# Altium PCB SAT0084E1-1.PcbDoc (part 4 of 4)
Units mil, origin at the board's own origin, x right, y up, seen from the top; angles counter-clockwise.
Board outline 7055 x 5555 mil, 6 copper layers (Top Layer, MidLayer1-GND, MidLayer2-HiSp, MidLayer3-GND, MidLayer4, Bottom Layer), stack 57.4 mil thick; 379 components, 207 nets, 1026 pads, 1546 vias.
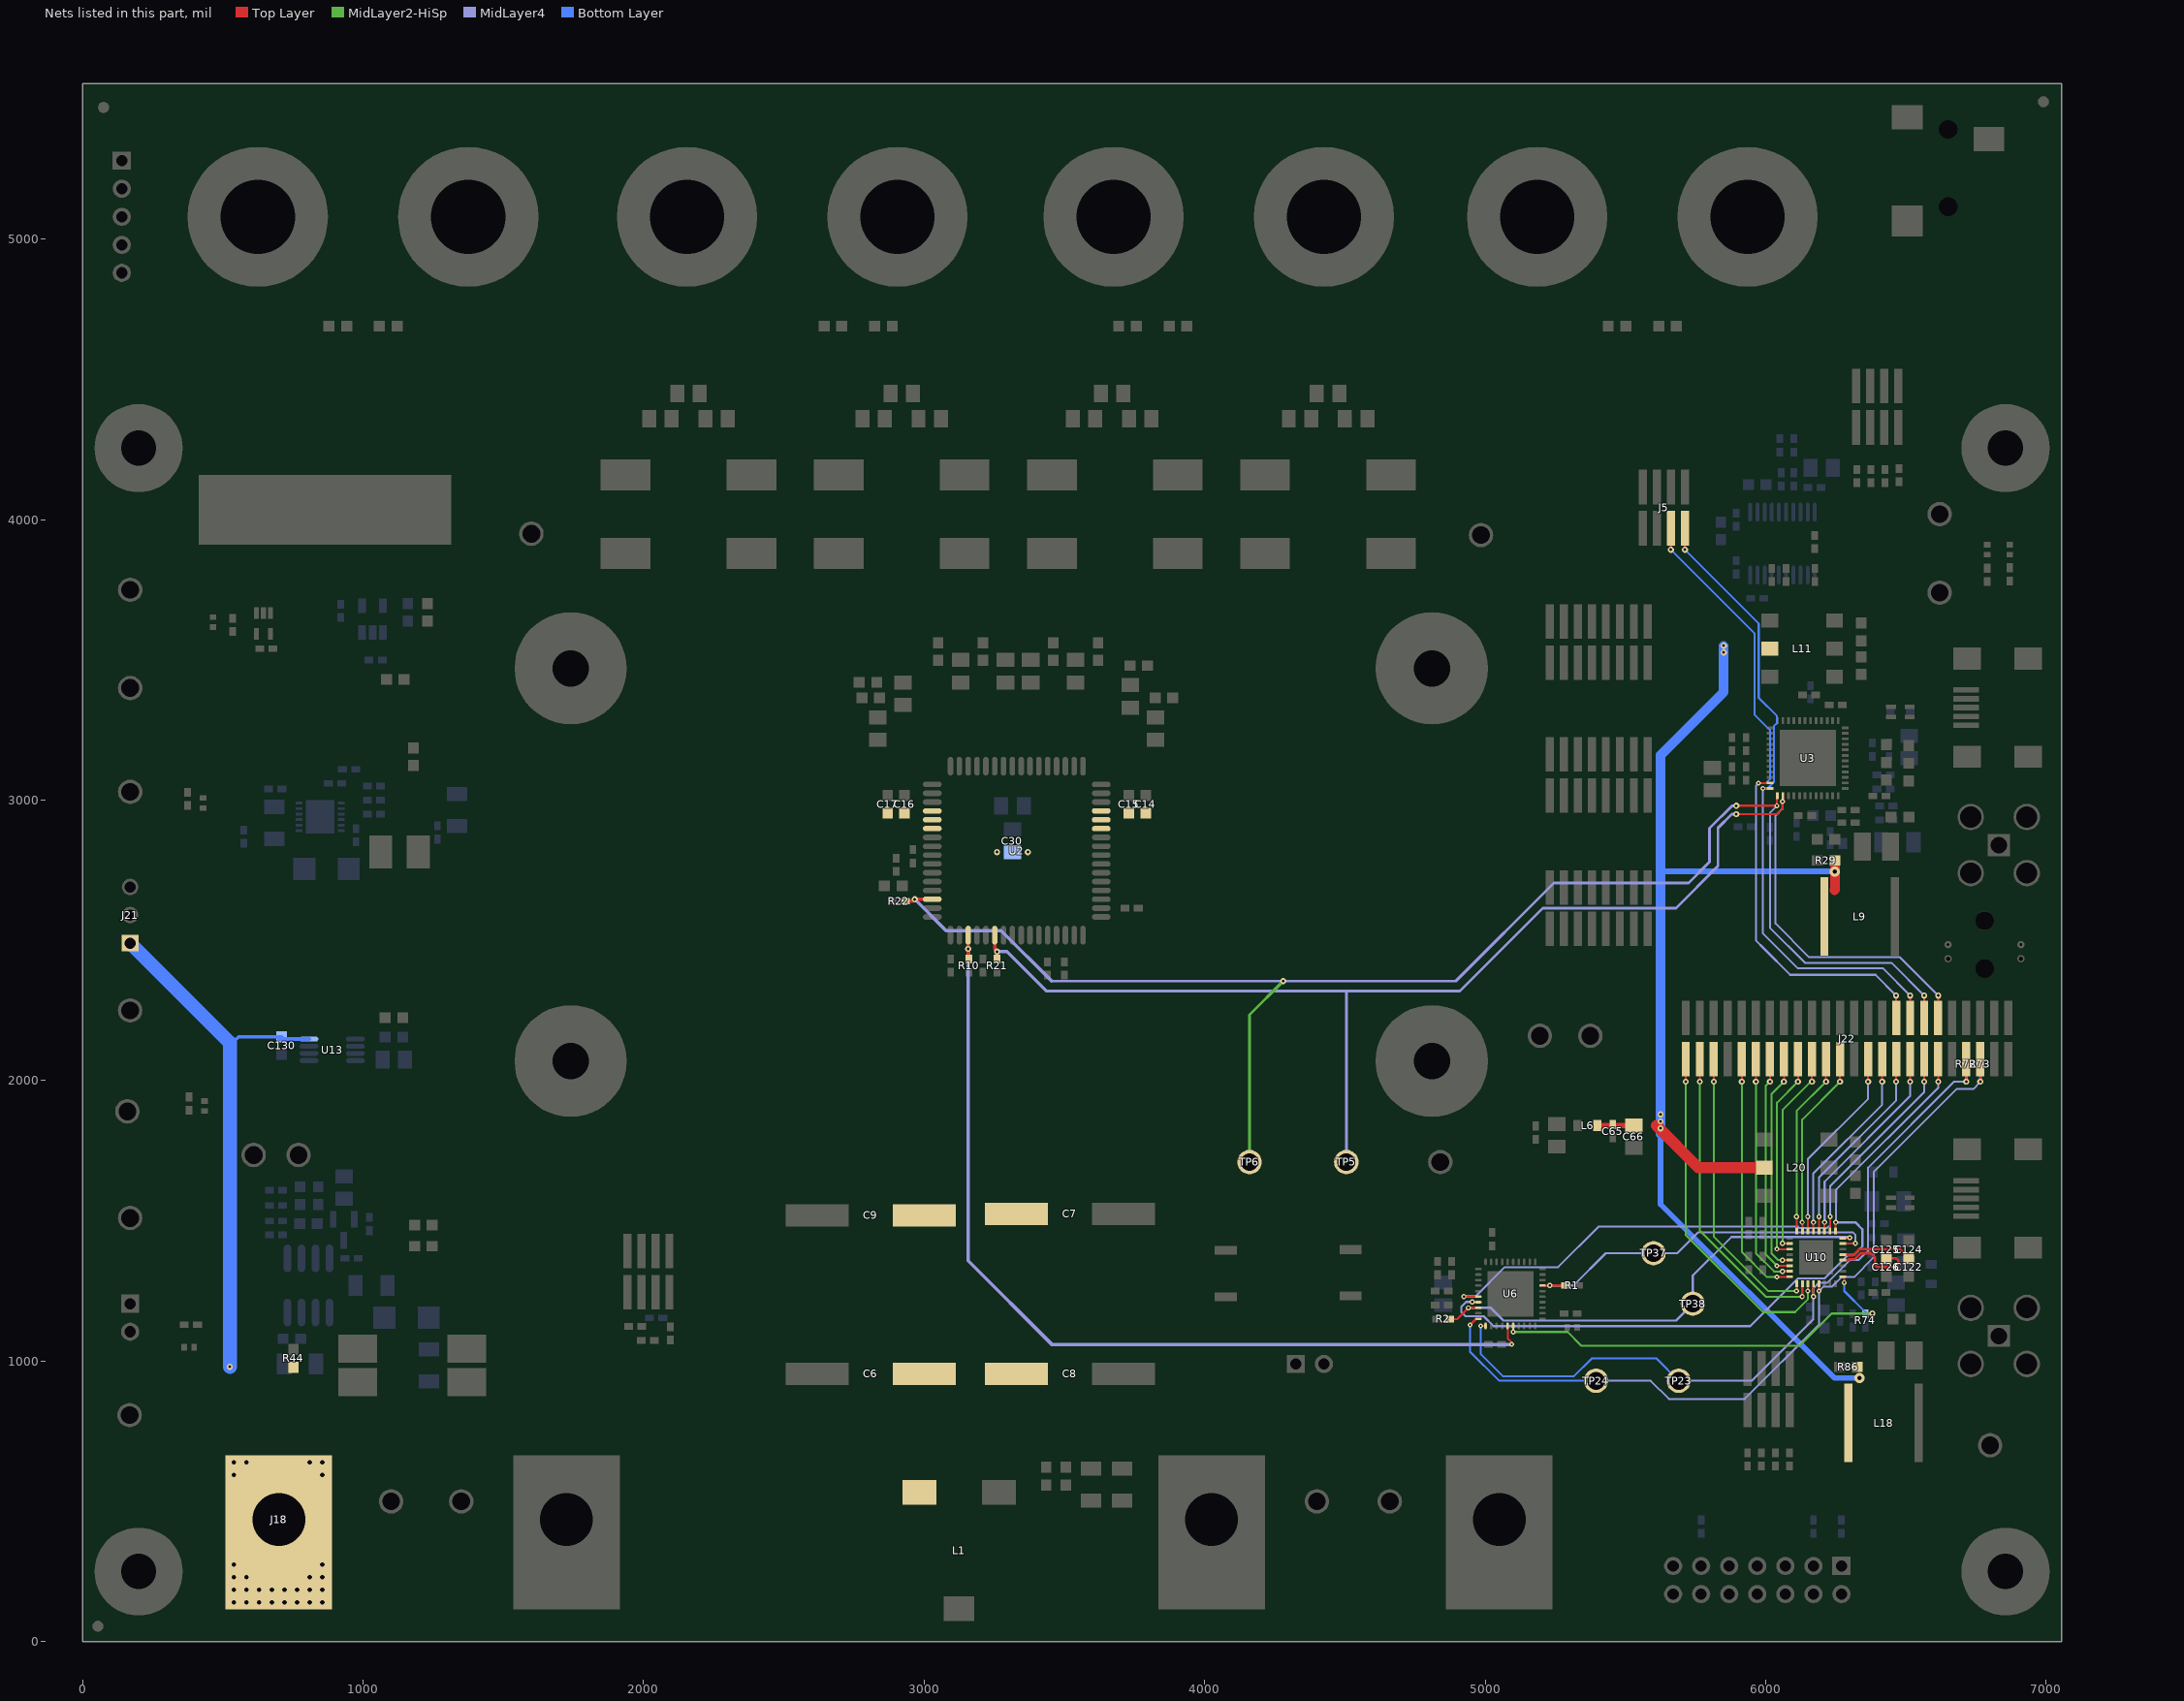
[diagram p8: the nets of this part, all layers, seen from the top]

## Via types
v1: diameter 22, hole 10, Top Layer to Bottom Layer, tented both sides, 1179 vias
v2: diameter 48, hole 22, Top Layer to Bottom Layer, tented both sides, 128 vias
v3: diameter 32, hole 16, Top Layer to Bottom Layer, tented both sides, 112 vias
v4: diameter 18, hole 8, Top Layer to Bottom Layer, tented both sides, 80 vias
v5: diameter 19.68, hole 7.87, Top Layer to Bottom Layer, tented both sides, 30 vias
v6: diameter 26, hole 16, Top Layer to Bottom Layer, 12 vias
v7: diameter 36, hole 16, Top Layer to Bottom Layer, tented both sides, 2 vias
v8: diameter 26, hole 10, Top Layer to Bottom Layer, tented both sides, 1 vias
v9: diameter 20, hole 8, Top Layer to Bottom Layer, tented both sides, 1 vias
v10: diameter 30, hole 12, Top Layer to Bottom Layer, tented both sides, 1 vias

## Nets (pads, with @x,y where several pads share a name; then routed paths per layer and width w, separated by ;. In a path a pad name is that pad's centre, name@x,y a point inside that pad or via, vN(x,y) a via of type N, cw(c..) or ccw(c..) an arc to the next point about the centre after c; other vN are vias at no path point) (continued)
PCM_MUTE_2: J5.5 J22.32 U3.23 | length 2355.7
  Top Layer w7: v4@5974,3061.42 U3.23@6016.14,3061.42
  Top Layer w8: v1(5662,3893) J5.5@5662,3969.48 ; J22.32@6465,2223.52 v1(6465,2303.52)
  MidLayer4 w7: v4(5974,3061) 5965,3052 5965,2500 5995,2470
  MidLayer4 w8: 5995,2470 6087.5,2377.5 6391.02,2377.5 v1(6465,2303.52)
  Bottom Layer w7: v1(5662,3893) 5960,3595 5960,3305 6015,3250 6015,3075 6001.37,3061.37 5974.37,3061.37 v4(5974,3061)
PCM_MUTE_3: J5.7 J22.34 U3.24 | length 2333.7
  Top Layer w7: v1(5712,3893) J5.7@5712,3969.48 ; v4@5990,3042 v4(5990.13,3041.87) 5990.27,3041.73 U3.24@6016.14,3041.73 ; J22.34@6515,2223.52 v1(6515,2303.52)
  MidLayer4 w7: v4(5990.13,3041.87) 5990.13,2524.87 6115,2400 6418.52,2400 v1(6515,2303.52)
  Bottom Layer w7: v1(5712,3893) 5975,3630 5975,3365 6040,3300 6040,3275 6030,3265 6030,3065 6006.87,3041.87 v4(5990.13,3041.87)
POC: C65.1 C66.1 L6.2 L9.1 L11.5 L18.1 L20.5 R29.2 R86.2 | length 4356.5
  Top Layer w20: L6.2@5400,1845 5405,1840 C66.1@5530,1840
  Top Layer w35: 6245,2680 6246.5,2681.5 R29.2@6246.5,2785
  Top Layer w40: 5610,1840 5760,1690 L20.5@5994.84,1690
  Bottom Layer w20: 5625,1810 5625.5,1809.5 5625.5,1559.5 6245,940 v7(6335,940) ; 5625,2744 5627,2746 v7(6246,2746)
  Bottom Layer w35: 5625,1810 v1(5625,1830) v1(5625,1855) v1(5625,1880) 5625,2744 5625,3160 5850,3385 v1@5850,3550
  other v1: 5850,3527 5850,3551
PVDD: C6.1 C7.1 C8.1 C9.1 C14.1 C15.1 C16.1 C17.1 C30.1 L1.2 U2.27 U2.28 U2.29 U2.52 U2.53 U2.54
  other v1: 3260,2815 3370,2815
SER_CLIP_OTW: J22.37 U6.7 U10.17 | length 2584.8
  Top Layer w7: v4(4954,1211) 4954.53,1210.47 U6.7@4975.83,1210.47 ; U10.17@6248.9,1464.49 v4@6248.9,1488.9 ; v4@6248.9,1493.9 v4(6250,1495) ; v1(6615,1996.48) J22.37@6615,2076.48
  MidLayer4 w7: v4@6250,1490 v4(6250,1495) 6250,1610 6615,1975 v1(6615,1996.48)
  MidLayer4 w8: v4(4954,1211) 4932,1211 4915,1194 4915,1175 4930,1160 4995,1160 5030,1125 5945,1125 6115,1295 6210,1295 6295,1380 6315,1380 6345,1410 6345,1470 6320,1495 v4(6250,1495)
SER_DOUT_N: C125.1 C126.1 U10.12 | length 309.9
  Top Layer w9: U10.12@6274.49,1360.16 6294,1360.16 6296.84,1363 6316.8,1363 6338.8,1385 6375,1385 6390,1370 6390,1343 6398,1335 6465,1335 6472,1342 6472,1360 6465.5,1366.5 C125.1@6430,1366.5
SER_DOUT_P: C122.1 C124.1 U10.13 | length 265.4
  Top Layer w9: U10.13@6274.49,1379.84 6294,1379.84 6296.84,1377 6311,1377 6333,1399 6479.5,1399 C122.1@6510,1368.5 ; C122.1@6503,1365 C122.1@6510,1365
SER_FAULT: J22.35 U6.6 U10.18 | length 2242.4
  Top Layer w7: v4@4924,1230.5 4975.48,1230.5 U6.6@4975.83,1230.16 ; U10.18@6229.21,1464.49 6229.5,1464.78 v4@6229.5,1509.5 ; v4@6229.5,1514.5 v4(6230,1515) ; v1(6565,1996.48) J22.35@6565,2076.48
  MidLayer4 w7: v4@4924,1232 4967,1232 5070,1335 5260,1335 5405,1480 6114,1480 6119,1475 6219,1475 6230,1486 6230,1625 6565,1960 v1(6565,1996.48)
  other v4: 4924,1230
SER_GPO2: R2.2 TP38.1 U6.8 U10.16 | length 1706.6
  Top Layer w7: U10.16@6274.49,1438.9 6298.9,1438.9 v4(6300,1440)
  Top Layer w8: R2.2@4873.62,1150 4900,1150 v4(4940,1190) v4@4945,1190 ; v4@4945,1190.79 U6.8@4975.83,1190.79
  MidLayer4 w8: v4(4940,1190) 5020,1190 5065,1145 5680,1145 TP38.1@5740,1205 5740,1305 5878,1443 6297,1443 v4(6300,1440)
SER_GPO3: R1.2 TP37.1 U6.27 U10.15 | length 1331.1
  Top Layer w7: U6.27@5204.17,1269.53 5229.53,1269.53 v4(5230,1270) R1.2@5286.38,1270 ; U10.15@6274.49,1419.21 6274.78,1419.5 6319.5,1419.5 v4(6320,1420)
  MidLayer4 w7: v4(5230,1270) 5315,1270 5430,1385 TP37.1@5600,1385 5685,1385 5760,1460 6310,1460 6320,1450 v4(6320,1420)
SER_I2C_SCL: J22.41 R72.1 TP23.1 U6.11 U10.4 | length 2786.1
  Top Layer w7: v4(6170,1230) 6170.16,1230.16 U10.4@6170.16,1275.51 ; v1(6715,1996.48) J22.41@6715,2076.48
  Top Layer w8: v4(4984,1126) 4984.17,1125.83 U6.11@5001.42,1125.83
  MidLayer4 w7: TP23.1@5690,930 5950,930 6170,1150 v4(6170,1230) 6170,1260 6190,1280 6220,1280 6300,1360 6330,1360 6365,1395 6365,1690 6671.48,1996.48 v1(6715,1996.48)
  Bottom Layer w7: v4(4984,1126) 4984,1026 5064.38,945.62 5315.62,945.62 5380,1010 5610,1010 TP23.1@5690,930
  Bottom Layer w10: v1(6715,1996.48) R72.1@6715,2036.38
SER_I2C_SDA: J22.43 R73.1 TP24.1 U6.10 U10.5 | length 2887.1
  Top Layer w7: U10.5@6189.84,1275.51 6189.84,1250.16 v4(6190,1250) ; v1(6765,1996.48) J22.43@6765,2076.48
  Top Layer w8: v4(4946,1129) 4968.42,1151.42 U6.10@4975.83,1151.42
  MidLayer4 w7: TP24.1@5435,930 5590,930 5655,865 5925,865 6190,1130 v4(6190,1250) 6205,1265 6235,1265 6270,1300 6315,1300 6385,1370 6385,1675 6680,1970 6740,1970 6765,1995 v1(6765,1996.48)
  Bottom Layer w7: v4(4946,1129) 4946,1034 5050,930 TP24.1@5435,930
  Bottom Layer w10: v1(6765,1996.48) R73.1@6765,2036.38
SER_I2S_BCK: J22.5 U10.1 | length 1033.2
  Top Layer w7: v1(5815,1996.48) J22.5@5815,2076.48 ; v4(6110,1250) 6111.1,1251.1 U10.1@6111.1,1275.51
  MidLayer2-HiSp w7: v1(5815,1996.48) 5815,1445 6010,1250 v4(6110,1250)
SER_I2S_DATA0: J22.9 U10.32 | length 894.7
  Top Layer w7: v1(5915,1996.48) J22.9@5915,2076.48 ; v4(6040,1300) 6040.5,1300.5 6084.91,1300.5 U10.32@6085.51,1301.1
  MidLayer2-HiSp w7: v1(5915,1996.48) 5915,1390 6005,1300 v4(6040,1300)
SER_I2S_DATA1: J22.11 U10.31 | length 837.8
  Top Layer w7: v1(5965,1996.48) J22.11@5965,2076.48 ; v4(6060,1320) 6060.79,1320.79 U10.31@6085.51,1320.79
  MidLayer2-HiSp w7: v1@5965,1995 5965,1385 6030,1320 v4(6060,1320)
SER_I2S_DATA2: J22.13 U10.30 | length 805
  Top Layer w7: v1(6015,1996.48) J22.13@6015,2076.48 ; v4(6040,1340) 6040.47,1340.47 U10.30@6085.51,1340.47
  MidLayer2-HiSp w7: v1(6015,1996.48) 6000,1981.48 6000,1380 v4(6040,1340)
SER_I2S_DATA3: J22.15 U10.29 | length 786
  Top Layer w7: v4(6060,1360) 6060.16,1360.16 U10.29@6085.51,1360.16 ; v1(6065,1996.48) J22.15@6065,2076.48
  MidLayer2-HiSp w7: v4(6060,1360) 6045,1360 6020,1385 6020,1951.48 v1(6065,1996.48)
SER_I2S_DATA4: J22.17 U10.27 | length 753.2
  Top Layer w7: v4(6040,1400) 6040.47,1399.53 U10.27@6085.51,1399.53 ; v1(6115,1996.48) J22.17@6115,2076.48
  MidLayer2-HiSp w7: v4(6040,1400) 6040,1921.48 v1(6115,1996.48)
SER_I2S_DATA5: J22.19 U10.26 | length 729.3
  Top Layer w7: v4(6060,1420) 6060.79,1419.21 U10.26@6085.51,1419.21 ; v1(6165,1996.48) J22.19@6165,2076.48
  MidLayer2-HiSp w7: v4(6060,1420) 6060,1895 6160,1995 v1@6165,1990
SER_I2S_DATA6: J22.21 U10.24 | length 655.9
  Top Layer w7: v4(6110,1515) v4@6110.5,1514.5 ; v4@6110.5,1509.5 6110.5,1465.09 U10.24@6111.1,1464.49 ; v1(6215,1996.48) J22.21@6215,2076.48
  MidLayer2-HiSp w7: v4@6110,1510 v4(6110,1515) 6110,1891.48 v1(6215,1996.48)
SER_I2S_DATA7: J22.23 U10.23 | length 668.2
  Top Layer w7: v4(6130,1495) v4@6130.79,1494.21 ; U10.23@6130.79,1464.49 v4@6130.79,1489.21 ; v1(6265,1996.48) J22.23@6265,2076.48
  MidLayer2-HiSp w7: v4@6130,1490 v4(6130,1495) 6130,1861.48 v1(6265,1996.48)
SER_I2S_LRCK: J22.3 U10.2 | length 1119.7
  Top Layer w7: v1(5765,1996.48) J22.3@5765,2076.48 ; v4(6130,1230) 6130.5,1230.5 6130.5,1275.22 U10.2@6130.79,1275.51
  MidLayer2-HiSp w7: v1(5765,1996.48) 5765,1465 6000,1230 v4(6130,1230)
SER_I2S_SCK: J22.1 U10.3 | length 1249.7
  Top Layer w7: v1(5715,1996.48) J22.1@5715,2076.48 ; v4(6150,1250) 6150.47,1250.47 U10.3@6150.47,1275.51
  MidLayer2-HiSp w7: v1(5715,1996.48) 5715,1957.35 5715,1450 5990,1175 6105,1175 6150,1220 v4(6150,1250)
SER_MUTE_0: J22.27 U10.22 | length 701.2
  Top Layer w7: v4(6150,1515) v4@6150.47,1514.53 ; U10.22@6150.47,1464.49 v4@6150.47,1509.53 ; v1(6365,1996.48) J22.27@6365,2076.48
  MidLayer4 w7: v4@6150,1510 6150,1720 6365,1935 v1(6365,1996.48)
SER_MUTE_1: J22.29 U10.21 | length 713.5
  Top Layer w7: v4(6170,1495) v4@6170.16,1494.84 ; U10.21@6170.16,1464.49 v4@6170.16,1489.84 ; v1(6415,1996.48) J22.29@6415,2076.48
  MidLayer4 w7: v4@6170,1490 6170,1670 6415,1915 v1(6415,1996.48)
SER_MUTE_2: J22.31 U10.20 | length 726
  Top Layer w7: U10.20@6189.84,1464.49 v4@6189.84,1509.84 ; v4@6189.84,1514.84 v4(6190,1515) ; v1(6465,1996.48) J22.31@6465,2076.48
  MidLayer4 w7: v4@6190,1510 6190,1655 6465,1930 v1(6465,1996.48)
SER_MUTE_3: J22.33 U10.19 | length 738.5
  Top Layer w7: U10.19@6209.53,1464.49 v4@6209.53,1489.53 ; v4@6209.53,1494.53 v4(6210,1495) ; v1(6515,1996.48) J22.33@6515,2076.48
  MidLayer4 w7: v4@6210,1490 6210,1640 6515,1945 v1(6515,1996.48)
SER_PDB: R74.1 U6.16 U10.9 | length 1563.8
  Top Layer w7: U6.16@5099.84,1125.83 5099.84,1104.16 v4(5100,1104) ; U10.9@6274.49,1301.1 6278.9,1301.1 6280,1300 v4(6280,1280)
  MidLayer2-HiSp w8: v4(5100,1104) 5294,1104 5343,1055 6120,1055 6235,1170 v1(6380,1170)
  Bottom Layer w8: v4(6280,1280) 6280,1250 6355,1175 R74.1@6355,1168.62
  Bottom Layer w10: R74.1@6355,1168.62 6378.62,1168.62 v1(6380,1170)
TAS_CLIP_OTW: J22.38 R21.1 TP5.1 U2.6 U3.26 | length 5163.9
  Top Layer w7: v4(6060,2995) 6061.42,2996.42 U3.26@6061.42,3016.14 ; J22.38@6615,2223.52 v1(6615,2303.52)
  Top Layer w8: v1(5895,2950) 6040,2950 6060,2970 v4(6060,2995)
  Top Layer w12: U2.6@3251.57,2518.82 3251.57,2468.43 v1(3260,2460) R21.1@3260,2433.62
  MidLayer4 w7: v4(6060,2995) 6060,2970 6035,2945 6035,2560 6155,2440 6478.52,2440 v1(6615,2303.52)
  MidLayer4 w10: 3435,2320 4505,2320 ; TP5.1@4505,1710 4505,2320 ; v1(5895,2950) 5879,2950 5830,2901 5830,2765 5680,2615 5205,2615 4910,2320 4505,2320
  MidLayer4 w12: v1(3260,2460) 3295,2460 3435,2320
TAS_FAULT: J22.36 R22.1 TP6.1 U2.62 U3.25 | length 5528.5
  Top Layer w7: v4(6040,2980) 6040.5,2980.5 6040.5,3014.91 U3.25@6041.73,3016.14 ; J22.36@6565,2223.52 v1(6565,2303.52)
  Top Layer w8: v1(5895,2980) v4(6040,2980)
  Top Layer w12: R22.1@2933.62,2640 2960,2640 v1(2966.77,2646.77) U2.62@3029.13,2646.77
  MidLayer2-HiSp w10: TP6.1@4160,1710 4160,2235 v1(4280,2355)
  MidLayer4 w7: v4(6040,2980) 6015,2955 6015,2545 6140,2420 6448.52,2420 v1(6565,2303.52)
  MidLayer4 w10: 3455,2355 v1(4280,2355) 4895,2355 5245,2705 5725,2705 5800,2780 5800,2900 5880,2980 v1(5895,2980)
  MidLayer4 w12: v1(2966.77,2646.77) 3078.54,2535 3275,2535 3455,2355
TAS_STANDBY: R10.1 U2.3 U6.15 | length 3332.7
  Top Layer w7: U6.15@5080.16,1125.83 5080.16,1080.87 5095,1066.03 v4@5095,1065
  Top Layer w12: R10.1@3157.09,2426.54 v1(3157.09,2470) U2.3@3157.09,2518.82
  MidLayer4 w12: v1(3157.09,2470) 3157.09,1357.91 3455,1060 v4(5095,1060)
VBAT: C130.1 J18.1 J21.1 R44.1 U13.8 | length 1946.9
  Bottom Layer w12: 535,2135 556.5,2156.5 C130.1@710,2156.5
  Bottom Layer w15: C130.1@701.9,2148.39 U13.8@807.32,2148.39
  Bottom Layer w50: J21.1@169.87,2490.5 525,2135.37 v1(525,980)
  other v3: 540,140 585,140 630,140 675,140 720,140 765,140 810,140 855,140 540,185 585,185 630,185 675,185 720,185 765,185 810,185 855,185 540,230 585,230 810,230 855,230 540,275 855,275 540,595 855,595 540,640 585,640 810,640 855,640
pads on no net: FID1.1 FID2.1 FID3.1 FID4.1 FID5.1 FID6.1 H1.1 H2.1 H3.1 H4.1 H10.0 H11.0 H12.0 H13.0 H14.0 H15.0 H16.0 H17.0 J4.4 J4.5 J15.1 J15.4 J15.5 J17.6 J17.10 J17.12 J17.13 J17.14 J25.1 J25.4 J25.5 J26.MH1 J26.MH2 L1.3 L11.2 L11.4 L11.6 L20.2 L20.4 L20.6 SH-J21.0 SH-J24.0 SH-J27.0 U3.32 U3.33

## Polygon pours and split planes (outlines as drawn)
NetC97_2 on Top Layer "Top Layer-No Net 1" (solid, remove dead copper, pour order 43): 1105,2910 1105,2720 990,2720 990,2820 1020,2850 1065,2910
3V3 on Top Layer "Top Layer-No Net 1" (solid, remove dead copper, pour order 41): 5870,3135 5870,3110 6005.71,3110 6018.57,3119 6018.57,3123 6018.57,3134 6020,3135
1V8 on Top Layer "Top Layer-No Net 1" (solid, remove dead copper, pour order 40): 5920,3190 6025,3190 6025,3170 5965,3170 5960,3165 5870,3165 5870,3190
NetC28_1 on Top Layer "Top Layer-No Net 1" (solid, remove dead copper, pour order 57): 1105,5390 1100,5385 1100,4595 1190,4505 2240,4505 2265,4480 2265,4300 2295,4270 2295,4100 2475,4100 2475,4480 2235,4720 1925,4720 1650,4995 1650,5390
NetC31_2 on Top Layer "Top Layer-No Net 1" (solid, remove dead copper, pour order 59): 355,5390 355,4655 740,4270 1760,4270 1830,4200 1830,4095 2050,4095 2050,4485 1075,4485 900,4660 900,5390
NetC37_1 on Top Layer "Top Layer-No Net 1" (solid, remove dead copper, pour order 55): 2560,5390 2560,4880 2675,4765 2685,4755 2840,4755 2860,4735 2865,4730 2865,4665 2865,4645 3030,4480 3035,4475 3035,4105 3035,4100 3240,4100 3240,5390
NetC47_2 on Top Layer "Top Layer-No Net 1" (solid, remove dead copper, pour order 54): 3340,5390 3340,4100 3555,4100 3555,4480 3715,4640 3715,4720 3715,4725 3745,4755 3915,4755 3925,4755 4005,4835 4005,5390
NetC39_2 on Top Layer "Top Layer-No Net 1" (solid, remove dead copper, pour order 56): 1865,5390 1865,4900 2015,4750 2240,4750 2605,4385 2605,4100 2805,4100 2805,4525 2665,4665 2665,4725 2525,4865 2525,5390
NetC45_1 on Top Layer "Top Layer-No Net 1" (solid, remove dead copper, pour order 53): 3780,4100 3780,4530 3915,4665 3915,4710 4085,4880 4085,5390 4750,5390 4750,4965 4585,4800 4340,4800 4010,4470 4010,4100
NetC52_1 on Top Layer "Top Layer-No Net 1" (solid, remove dead copper, pour order 60): 6250,5390 6250,4655 5865,4270 4845,4270 4775,4200 4775,4095 4555,4095 4555,4485 5490,4485 5660,4655 5660,5390
OUT3_P on Top Layer "Top Layer-No Net 1" (solid, remove dead copper, pour order 44): 3462,3100 3462,3330 3507,3375 3562,3375 3562,3217 3515,3170 3497,3170 3482,3155 3482,3100
OUT4_M on Top Layer "Top Layer-No Net 1" (solid, remove dead copper, pour order 50): 3545,3095 3545,3155 3560,3170 3585,3170 3610,3195 3730,3195 3775,3240 3775,3295 3600,3295 3570,3265 3570,3215 3525,3170 3525,3095
OUT4_P on Top Layer "Top Layer-No Net 1" (solid, remove dead copper, pour order 49): 3790,3180 3610,3180 3585,3155 3555,3155 3555,3080 3745,3080 3750,3080 3790,3120
OUT1_M on Top Layer "Top Layer-No Net 1" (solid, remove dead copper, pour order 48): 2870,3180 3050,3180 3075,3155 3095,3155 3105,3145 3105,3080 2910,3080 2870,3120
OUT2_P on Top Layer "Top Layer-No Net 1" (solid, remove dead copper, pour order 46): 3245,3375 3210,3340 3210,3100 3230,3100 3230,3155 3245,3170 3270,3170 3310,3210 3310,3375
OUT3_M on Top Layer "Top Layer-No Net 1" (solid, remove dead copper, pour order 45): 3450,3100 3450,3330 3405,3375 3350,3375 3350,3210 3390,3170 3415,3170 3430,3155 3430,3100
OUT2_M on Top Layer "Top Layer-No Net 1" (solid, remove dead copper, pour order 47): 3100,3375 3100,3220 3150,3170 3160,3170 3175,3155 3175,3095 3200,3095 3200,3340 3165,3375
OUT1_P on Top Layer "Top Layer-No Net 1" (solid, remove dead copper, pour order 51): 3115,3095 3115,3155 3100,3170 3075,3170 3040,3205 2921,3205 2885,3241 2885,3306 3049,3306 3085,3270 3085,3215 3135,3165 3135,3095
NetC54_2 on Top Layer "Top Layer-No Net 1" (solid, remove dead copper, pour order 58): 5455,5390 5455,4550 5410,4505 4360,4505 4335,4480 4335,4300 4305,4270 4305,4100 4125,4100 4125,4500 4380,4755 4615,4755 4845,4985 4845,5390
3V3 on Top Layer "Top Layer-No Net 1" (solid, remove dead copper, pour order 42): 5930,1435 6095,1435 6095,1445 6075,1445 6055,1465 5930,1465
VBAT on Top Layer "Top Layer-No Net 1" (solid, remove dead copper, pour order 52): 505,115 500,120 500,1000 785,1000 785,870 890,765 890,115
PVDD on Top Layer "Top Layer-No Net 1" (solid, remove dead copper, pour order 61): 2810,485 3055,485 3150,580 3150,610 3205,665 3235,665 3520,950 3520,1575 3690,1745 4010,1745 4250,1985 4250,2875 4150,2975 3485,2975 3355,2845 3355,2790 3395,2790 3490,2885 3755,2885 3885,2755 3885,2550 3655,2320 3025,2320 2795,2550 2795,2800 2880,2885 3130,2885 3225,2790 3275,2790 3275,2845 3145,2975 2485,2975 2385,2875 2385,2000 2810,1575
GND on Top Layer "Top Layer-No Net 1" (solid, remove dead copper, pour order 62): 25,5525 7025,5525 7025,25 25,25
OUT1_M on MidLayer2-HiSp "Top Layer-No Net 1" (solid, remove dead copper, pour order 67): 2010,3960 2010,3700 2130,3580 2370,3580 2880,3070 3080,3070 3080,3130 3020,3190 2920,3190 2870,3240 2870,3310 2460,3720 2170,3720 2150,3740 2150,3960
OUT2_M on MidLayer2-HiSp "Top Layer-No Net 1" (solid, remove dead copper, pour order 64): 2770,3960 2770,3710 2880,3600 2990,3600 3080,3510 3080,3240 3150,3170 3200,3170 3200,3580 3050,3730 2960,3730 2910,3780 2910,3960
OUT3_M on MidLayer2-HiSp "Top Layer-No Net 1" (solid, remove dead copper, pour order 65): 3340,3210 3340,3460 3410,3530 3470,3530 3530,3590 3530,3960 3670,3960 3670,3470 3600,3400 3500,3400 3450,3350 3450,3170 3380,3170
OUT4_M on MidLayer2-HiSp "Top Layer-No Net 1" (solid, remove dead copper, pour order 66): 3570,3260 3630,3320 3920,3320 4290,3690 4290,3960 4430,3960 4430,3560 4060,3190 3570,3190
GND on MidLayer3-GND "Top Layer-No Net 1" (solid, remove dead copper, pour order 72): 25,5525 7025,5525 7025,25 25,25
OUT4_P on MidLayer3-GND "Top Layer-No Net 1" (solid, remove dead copper, pour order 71): 3620,3180 3580,3140 3580,3070 3940,3070 4590,3720 4590,3960 4450,3960 4450,3770 4420,3740 4340,3740 3835,3235 3790,3235 3735,3180
OUT3_P on MidLayer3-GND "Top Layer-No Net 1" (solid, remove dead copper, pour order 69): 3460,3170 3460,3520 3530,3590 3530,3670 3590,3730 3650,3730 3690,3770 3690,3960 3830,3960 3830,3730 3670,3570 3670,3470 3560,3360 3560,3210 3520,3170
OUT2_P on MidLayer3-GND "Top Layer-No Net 1" (solid, remove dead copper, pour order 68): 3210,3170 3210,3340 3170,3380 3080,3380 3080,3510 2930,3660 2930,3960 3070,3960 3070,3710 3200,3580 3200,3490 3320,3370 3320,3220 3270,3170
OUT1_P on MidLayer3-GND "Top Layer-No Net 1" (solid, remove dead copper, pour order 70): 2170,3960 2170,3650 2240,3580 2370,3580 2760,3190 3090,3190 3090,3250 3020,3320 2860,3320 2460,3720 2330,3720 2310,3740 2310,3960
GND on MidLayer4 "Top Layer-No Net 1" (solid, remove dead copper, pour order 73): 6354,3150 6565,3150 6665,3050 6665,2840 6975,2530 6975,2390 6665,2390 6500,2555 6500,2965 6450,3015 6305,3015 6305,3101
NetC97_2 on Bottom Layer "Top Layer-No Net 1" (solid, remove dead copper, pour order 76): 910,2895 910,2715 1020,2715 1020,2810 1010,2820 960,2820 950,2830 950,2885 940,2895
NetC92_1 on Bottom Layer "Top Layer-No Net 1" (solid, remove dead copper, pour order 75): 805,1025 850,1025 870,1045 870,1065 880,1075 910,1075 910,995 890,995 865,970 865,930 860,925 805,925
NetC90_2 on Bottom Layer "Top Layer-No Net 1" (solid, remove dead copper, pour order 77): 870,1220 870,1130 1100,900 1235,900 1235,955 1170,955 905,1220
NetC98_1 on Bottom Layer "Top Layer-No Net 1" (solid, remove dead copper, pour order 74): 650,2885 650,2835 725,2835 770,2880 785,2880 785,2895 660,2895
GND on Bottom Layer "Top Layer-No Net 1" (solid, remove dead copper, pour order 78): 25,5525 7025,5525 7025,25 25,25
GND on MidLayer1-GND "Top Layer-No Net 1" (solid, remove dead copper, pour order 63): 25,5525 7025,5525 7025,25 25,25

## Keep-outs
Keep-Out Layer:
  lines w10: -5,0 ccw(c0,0) 0,-5 ; -5,0 ccw(c0,0) 0,-5 ; -5,0 -5,5555 ; -5,5555 cw(c0,5555) 0,5560 ; -5,5555 cw(c0,5555) 0,5560 ; 0,-5 7055,-5 ; 0,5560 7055,5560 ; 7055,-5 ccw(c7055,0) 7060,0 ; 7055,-5 ccw(c7055,0) 7060,0 ; 7055,5560 cw(c7055,5555) 7060,5555 ; 7055,5560 cw(c7055,5555) 7060,5555 ; 7060,0 7060,5555
  text ".Layer_Name" at 577,-858.49 h60

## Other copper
Top Layer:
  rectangle net GND: 910,845 1050,975
  rectangle net NetC92_1: 730,1016 856,1062
  rectangle net POC: 5500,1815 5645,1900
  rectangle net POC: 5835,3515 6045,3565
  rectangle net NetC10_1: 3205,110 4215,580
  rectangle net 3V3: 5833,3104 5889,3138
  rectangle net OUT1_M: 1845,3805 2130,3955
  rectangle net OUT1_P: 2190,3805 2475,3955
  rectangle net OUT2_M: 2605,3805 2890,3955
  rectangle net OUT2_P: 2950,3805 3235,3955
  rectangle net OUT3_M: 3365,3805 3650,3955
  rectangle net OUT3_P: 3710,3805 3995,3955
  rectangle net OUT4_M: 4125,3805 4410,3955
  rectangle net OUT4_P: 4470,3805 4755,3955
  region net 3V3: 1210,3450 1125,3450 1125,3165 1210,3165
  rectangle net NetC101_1: 1045,3405 1105,3485
  rectangle net NetC102_1: 1180,3675 1250,3730
  rectangle net 8V: 5090,1825 5190,1855
  rectangle net 8V: 1225,1390 1335,1505
  rectangle net NetC92_1: 805,925 860,1062
  rectangle net NetC90_1: 1270,995 1440,1095
  rectangle net NetC90_2: 1270,875 1440,975
  rectangle net NetC92_1: 880,995 1050,1095
  rectangle net NetC91_1: 1040,1375 1205,1430
  rectangle net NetL14_2: 1155,2855 1240,3145
  rectangle net POC: 6300,880 6360,1000
  rectangle net NetL14_2: 1160,2760 1275,2855
  rectangle net GND: 6241,3155 6295,3184
  pour cut-out: 930,1230 1420,1230 1420,740 905,740 905.39,979.65 930,1005
  pour cut-out: 6293.66,2445.24 6376.34,2445.24 6376.34,2424.84 6293.66,2424.84
  pour cut-out: 6378.66,640.24 6461.34,640.24 6461.34,619.84 6378.66,619.84
  pour cut-out: 6550,1072.66 6550,1155.34 6570.39,1155.34 6570.39,1072.66
  pour cut-out: 1137.24,2923.34 1137.24,2840.66 1116.84,2840.66 1116.84,2923.34
  pour cut-out: 1091.66,2722.24 1174.34,2722.24 1174.34,2701.84 1091.66,2701.84
  text ".CopyrightYear" at 727,3805 h60
  text "TI" at 1003,3805 h60
  text "©" at 610,3801.48 h105
  text ".Layer_Name" at 577,-858.49 h60
MidLayer1-GND:
  text ".Layer_Name" at 577,-858.49 h60
MidLayer2-HiSp:
  rectangle net NetC10_1: 3205,110 4215,580
  text ".Layer_Name" at 577,-858.49 h60
MidLayer3-GND:
  text ".Layer_Name" at 577,-858.49 h60
MidLayer4:
  text ".Layer_Name" at 577,-858.49 h60
Bottom Layer:
  rectangle net PVDD: 3245,2790 3385,2840
  rectangle net NetC101_1: 1045,3455 1100,3515
  rectangle net NetC102_1: 1140,3675 1210,3730
  rectangle net NetC90_1: 1195,1015 1300,1070
  rectangle net NetC90_2: 1195,900 1300,955
  rectangle net NetC90_1: 1195,1015 1275,1195
  rectangle net NetC91_1: 1040,1115 1115,1430
  rectangle net GND: 760,2945 800,2975
  rectangle net GND: 720,2950 765,2975
  rectangle net NetC100_1: 1255,2885 1370,2930
  rectangle net NetL14_2: 1245,2755 1275,2875
  text ".Layer_Name" at 577,-858.49 h60

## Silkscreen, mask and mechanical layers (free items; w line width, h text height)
Top Overlay:
  region: 1530,4470 1230,4470 1230,4370 1530,4370
  lines w10: 1500,1869 5044,1869 5044,3680 1500,3680 1500,1869
  text "Phase shedding" at 250,4815 h40 r90
  text "CH3" at 3425,4725 h40
  text "CH1" at 350,4720 h40
  text "CH4" at 4940,4715 h40
  text "CH2" at 1970,4710 h40
  text ".PRJ_Number" at 564,4380 h60
  text ".PCB_Rev" at 1000,4380 h60
  text "Addr DeSer" at 6225,4218 h40
  text "Lock" at 6747,3867 h40 r90
  text "Pass" at 6943,3865 h40 r90
  text "Mute PCM" at 5495,3825 h40
  text "DIN PCM" at 5275,3350 h40
  text "DeSer" at 6636,3251 h40 r90
  text "DIN1 TAS" at 5255,2880 h40
  text "DeSer" at 6661,2681 h40 r90
  text "DIN2 TAS" at 5255,2410 h40
  text "+" at 6587,2370 h40 r180
  text "Input Select" at 300,2360 h40 r90
  text "_" at 6960,2356 h40
  text "Ser" at 6637,1533 h40 r90
  text "ADDR TAS" at 1875,1474 h40
  text "Ser" at 6664,965 h40 r90
  text "Master/Slave" at 4140,885 h40
  text "Addr Ser" at 5862,710 h40
  text "24V" at 3960,700 h40
  text "GND" at 4990,700 h40
  text "VBAT" at 620,690 h40
  text "GND" at 1670,690 h40
  text "JTAG" at 5890,415 h40
  text ".Layer_Name" at 577,-858.49 h60
Bottom Overlay:
  text ".Layer_Name" at 577,-858.49 h60
Top Paste:
  text ".Layer_Name" at 577,-858.49 h60
Bottom Paste:
  text ".Layer_Name" at 577,-858.49 h60
Top Solder:
  text ".Layer_Name" at 577,-858.49 h60
  text ".Layer_Name" at 577,-858.49 h60
Bottom Solder:
  text ".Layer_Name" at 577,-858.49 h60
Drill Guide:
  text ".Layer_Name" at 577,-858.49 h60
M1 Board Outline:
  the board outline again, w10
  text ".Layer_Name" at 577,-858.49 h60
M2 Board Dimensions:
  rectangle: 124.5,-410.5 499.5,-285.5
  rectangle: -0.5,-285.5 124.5,-160.5
  lines w7: -0.5,-285.5 999.5,-285.5 ; 124.5,-410.5 124.5,-160.5 ; 249.5,-410.5 249.5,-160.5 ; 499.5,-410.5 499.5,-160.5 ; 749.5,-410.5 749.5,-160.5 ; -0.5,-410.5 -0.5,-160.5 999.5,-160.5 999.5,-410.5 -0.5,-410.5
  lines w10: -0.5,-475.5 -0.5,-455.5 ; 59.5,-485.5 -0.5,-465.5 ; 59.5,-445.5 -0.5,-465.5 ; 223.58,-465.5 -0.5,-465.5 ; 775.42,-465.5 999.5,-465.5 ; 939.5,-485.5 999.5,-465.5 ; 939.5,-445.5 999.5,-465.5 ; 999.5,-475.5 999.5,-455.5
  text "1000 (mil)" at 233.58,-501.49 h60
  text ".Layer_Name" at 577,-858.49 h60
M3 3D STEP Top:
  text ".Layer_Name" at 577,-858.49 h60
M4 3D STEP Bottom:
  text ".Layer_Name" at 577,-858.49 h60
M5 Assembly Top:
  lines w10: -292,-930.17 6308,-930.17 ; -292,-726.83 6310,-726.83 ; -292,-523.5 -292,-1133.5 3713,-1133.5 6310,-1133.5 6310,-523.5 -291.5,-523.5 -291.5,-1133.5 1284,-1133.5 ; 2173,-1133.5 2173,-523.5 ; 3440,-726.83 3440,-523.5 ; 4280,-726.83 4280,-523.5 ; 4902,-1140 4902,-937.17
  text "COMPONENTS MARKED 'DNP' SHOULD NOT BE POPULATED." at 1153.5,-318.5 h60
  text "ASSEMBLY VARIANT:" at 1153,-434 h60
  text ".VariantName" at 2189,-434 h60
  text "PCB VIEWED FROM TOP SIDE" at -228.5,-655.67 h60
  text "BOARD #:" at 2248,-655.67 h60
  text ".PRJ_Number" at 2793.5,-655.67 h60
  text "REV:" at 3638,-655.67 h60
  text ".PCB_Rev" at 3929.5,-655.67 h60
  text "SVN REV:" at 4476,-655.67 h60
  text ".VersionControl_RevNumber" at 4982,-655.67 h60
  text "IGNORE ->" at -228.5,-858.49 h60
  text "PLOT NAME =" at -228.5,-1064.34 h60
  text ".plot_File_Name" at 577,-1064.34 h60
  text "GENERATED    :" at 2250,-1064.34 h60
  text ".Print_Date" at 3119.5,-1064.34 h60
  text ".Print_Time" at 3848.5,-1064.34 h60
  text "TEXAS INSTRUMENTS" at 5113,-1064.34 h60
M6 Assembly Bottom:
  lines w10: -292.5,-727.33 6309.5,-727.33 ; -290.5,-930.67 6309.5,-930.67 ; 1115.5,-1140.5 1115.5,-937.67 ; 1737.5,-727.33 1737.5,-524 ; 2577.5,-727.33 2577.5,-524 ; 3844.5,-1134 3844.5,-524 ; 4733.5,-1134 6309,-1134 6309,-524 -292.5,-524 -292.5,-1134 2304.5,-1134 6309.5,-1134 6309.5,-524
  text "COMPONENTS MARKED 'DNP' SHOULD NOT BE POPULATED." at 6102,-318 h60
  text ".VariantName" at 5058,-434 h60
  text "ASSEMBLY VARIANT:" at 6097,-434 h60
  text ".VersionControl_RevNumber" at 1035.5,-656.17 h60
  text "SVN REV:" at 1541.5,-656.17 h60
  text ".PCB_Rev" at 2088,-656.17 h60
  text "REV:" at 2379.5,-656.17 h60
  text ".PRJ_Number" at 3224,-656.17 h60
  text "BOARD #:" at 3769.5,-656.17 h60
  text "PCB VIEWED FROM BOTTOM SIDE" at 6246,-656.17 h60
  text "IGNORE ->" at 2547.85,-858.49 h60
  text "TEXAS INSTRUMENTS" at 904.5,-1064.84 h60
  text ".Print_Time" at 2169,-1064.84 h60
  text ".Print_Date" at 2898,-1064.84 h60
  text "GENERATED    :" at 3767.5,-1064.84 h60
  text ".plot_File_Name" at 5440.5,-1064.84 h60
  text "PLOT NAME =" at 6246,-1064.84 h60
M9 Title Sheet:
  drawing of 57 lines, arcs and shapes, not listed
  text "1" at 739.84,8036.5 h70
  text "2" at 3235.5,8036.5 h70
  text "3" at 5724.84,8036.5 h70
  text "4" at 8231.51,8036.5 h70
  text "5" at 10730.5,8036.5 h70
  text "6" at 13235.5,8036.5 h70
  text "A" at -416.5,6893.5 h70
  text "A" at 14383.5,6893.5 h70
  text "B" at -416.5,4513.5 h70
  text "B" at 14383.5,4513.5 h70
  text "C" at -416.5,2138.5 h70
  text "C" at 14383.5,2138.5 h70
  text "PROJECT TITLE:" at 11343.5,277.5 h45
  text ".PRJ_Title" at 11393.5,144.17 h70
  text "DESIGNED FOR:" at 11343.5,-23.5 h45
  text ".PRJ_Customer" at 11393.5,-163.5 h70
  text "D" at -416.5,-231.5 h70
  text "D" at 14383.5,-231.5 h70
  text "FILE NAME:" at 11343.5,-323.5 h45
  text ".PCB_File_Name_No_Path" at 11393.5,-443.5 h70
  text "Texas Instruments (TI) and/or its licensors do not warrant the accuracy or completeness of this specification" at 6374,-605.34 h45
  text "ENGINEER:" at 11343.5,-613.5 h45
  text "LAYOUT BY:" at 12848.5,-613.5 h45
  text "or any information contained therein. TI and/or its licensors do not warrant that this design will meet" at 6329.01,-718 h45
  text ".PRJ_Engineer" at 11344.5,-760 h70
  text ".PCB_Layout" at 12850,-760 h70
  text "the specifications, will be suitable for your application or fit for any particular purpose, or will operate in" at 6329.01,-830.67 h45
  text ".Layer_Name" at 577,-858.49 h60
  text "ALTIUM DESIGNER VERSION:" at 12848.5,-923.5 h45
  text "an implementation. TI and/or its licensors do not warrant that the design is production worthy. You should" at 6329.01,-943.33 h45
  text "completely validate and test your design implementation to confirm the system functionality for your application." at 6374,-1056 h45
  text ".print_Scale" at 11393.5,-1056.83 h70
  text ".Application_BuildNumber" at 12899,-1056.83 h70
  text "1" at 739.84,-1263.5 h70
  text "2" at 3235.5,-1263.5 h70
  text "3" at 5724.84,-1263.5 h70
  text "4" at 8231.51,-1263.5 h70
  text "5" at 10730.5,-1263.5 h70
  text "6" at 13235.5,-1263.5 h70
M10 Fab Notes:
  drawing of 212 lines, arcs and shapes, not listed
  text "Top layer contains 100 Ohm differential pairs, 9mil trace, 5 mil spacing" at 7515,7505 h60
  text "Layer 3 contains 50 Ohm single ended high-speed lines, 7mil trace" at 7525,7360 h60
  text "Bottom layer contains 100 Ohm differential pair, 9mil trace, 5 mil spacing" at 7522.46,7223.64 h60
  text "DESIGN INFORMATION" at 12381.02,6810 h60
  text "(REFER ALSO ARRAY/PANEL PROFILING INFORMATION)" at 12019.46,6648.29 h60
  text "BOARD SIZE" at 11333.46,6644 h60
  text "5555MIL" at 11795.78,6516.18 h60
  text "X" at 12301.46,6516.18 h60
  text "7055MIL" at 12532.78,6516.18 h60
  text "Number of Layers :" at 11736.46,6319 h60
  text "6" at 12831.27,6309 h60
  text "MIN. TRACK WIDTH:" at 11736.46,6180 h60
  text "7" at 12832.7,6180 h60
  text "MIL" at 12987.46,6180 h60
  text "MIN. CLEARANCE:" at 11736.46,6048 h60
  text "5" at 12832.7,6048 h60
  text "MIL" at 12987.46,6048 h60
  text "MIN. VIA PAD SIZE:" at 11736.46,5916 h60
  text "18" at 12802.71,5916 h60
  text "MIL" at 12987.46,5916 h60
  text "0.05mm (2MIL)" at 12431.46,5774.29 h60
  text "MINIMUM ANNULAR RING" at 11407.23,5770 h60
  text "EXTERNAL" at 13139.46,5770 h60
  text "PER" at 11607.23,5652 h60
  text "IPC-D-275 CLASS 2 LEVEL C" at 11827.23,5652 h60
  text "MIL, HOLES" at 13315.46,5539.71 h60
  text "+/-" at 12923,5539 h60
  text "+/-" at 13777,5539 h60
  text "REGISTRATION TOLERANCES:" at 11407.23,5534 h60
  text "METAL" at 12607,5534 h60
  text "5" at 13183.2,5534 h60
  text "3" at 14016.2,5534 h60
  text "MIL" at 14132.46,5534 h60
  text "MATERIAL:" at 11332.46,5324.54 h60
  text "FR-4 High Tg" at 12318.9,5184.21 h60
  text "FR-408" at 11753.46,5175.64 h60
  text "X" at 12165.46,5175.64 h60
  text "OTHER" at 13241.46,5175.64 h60
  text "62 MIL (1.6mm) +/-10%" at 12073.56,5012.92 h60
  text "THICKNESS:" at 11407.23,5008.64 h60
  text "X" at 11945.4,5008.64 h60
  text "OTHER" at 13358.46,5008.64 h60
  text "TOLERANCE:" at 11407.23,4850.64 h60
  text "X" at 12246.53,4850.64 h60
  text "ANSI IPC-6012 TYPE 3 CLASS 2" at 12433.48,4850.64 h60
  text "OTHER +/-" at 12433.46,4694.64 h60
  text "BOW & TWIST:" at 11407.23,4537.64 h60
  text "X" at 12246.53,4537.64 h60
  text "ANSI IPC-6012 TYPE 3 CLASS 2" at 12433.48,4537.64 h60
  text "OTHER +/-" at 12433.46,4379.13 h60
  text "COPPER THICKNESS (FINISHED):" at 11332.46,4243.64 h60
  text "1.4MIL (1oz)" at 12212.46,4090.92 h60
  text "2MIL (1.4oz)" at 12979.46,4090.92 h60
  text "2.8MIL (2oz)" at 13706.46,4090.92 h60
  text "OUTER:" at 11689.46,4086.64 h60
  text "X" at 12084,4086 h60
  text "1.4MIL (1oz)" at 12212.46,3933.92 h60
  text "2.8MIL (2oz)" at 12979.46,3933.92 h60
  text "N/A" at 13706,3934.29 h60
  text "INNER SIGNAL:" at 11400.38,3929.64 h60
  text "X" at 12085.42,3929.64 h60
  text "DRILLING:" at 11332.46,3790.64 h60
  text "REFERENCE:" at 11407.23,3673.64 h60
  text "X" at 12055.46,3673.64 h60
  text "AS SHOWN" at 12242.46,3673.64 h60
  text "X" at 12956.46,3673.64 h60
  text "NC_DRILL FILES" at 13093.46,3673.64 h60
  text "PTH MIN COPPER THICKNESS:" at 11407.23,3515.64 h60
  text "X" at 12757.46,3515.64 h60
  text "1MIL" at 12894.46,3515.64 h60
  text "OTHER" at 13391.46,3515.64 h60
  text "BOARD FINISH:" at 11332.46,3356.64 h60
  text "SILKSCREEN:" at 11487.68,3238.64 h60
  text "X" at 12436.46,3238.64 h60
  text "TOP" at 12562.46,3238.64 h60
  text "X" at 12946.46,3238.64 h60
  text "BOTTOM" at 13073.46,3238.64 h60
  text "SILKSCREEN COLOR:" at 11487.68,3071.64 h60
  text "X" at 12435.42,3071.64 h60
  text "WHITE" at 12562.46,3071.64 h60
  text "OTHER" at 13073.46,3071.64 h60
  text "SOLDER RESIST COLOR:" at 11487.68,2901.64 h60
  text "X" at 12055.42,2742.44 h60
  text "GREEN" at 12182.46,2742.44 h60
  text "BLUE" at 12773.46,2742.44 h60
  text "OTHER" at 13311.46,2742.44 h60
  text "IMMERSION GOLD (ENIG)" at 12393.46,2553.92 h60
  text "ENEPIG" at 13731,2550.64 h60
  text "SURFACE FINISH:" at 11332.46,2549.64 h60
  text "X" at 12206.51,2549.64 h60
  text "IMM. TIN/SILVER OR EQUIV" at 11662,2392.64 h60
  text "OTHER" at 13093.46,2392.64 h60
  text "ARRAY/PANEL:" at 11332.46,2213.64 h60
  text "CUT AND TRIM PER MECH LAYER 1" at 12393.46,2209.35 h60
  text "N.C. ROUTE" at 12393.46,2057.64 h60
  text "X" at 13072.46,2057.64 h60
  text "V. SCORE" at 13259.46,2057.64 h60
  text "CERTIFICATION:" at 11332.46,1920.64 h60
  text "MATERIALS AND WORKMANSHIP FOR ALL PCBS" at 12057.46,1920.64 h60
  text "TO MEET OR EXCEED THE REQUIREMENTS OF:" at 12057.46,1822.64 h60
  text "X" at 11683.96,1686.13 h60
  text "ANSI IPC-A-600F CLASS ->" at 11822.96,1686.13 h60
  text "X" at 13462.02,1686.13 h60
  text "2" at 13580.96,1686.14 h60
  text "1" at 13265.96,1684.64 h60
  text "3" at 13934.96,1684.64 h60
  text "X" at 11686.02,1526.64 h60
  text "UL 94V-0" at 11822.96,1526.64 h60
  text "X" at 12498.02,1526.64 h60
  text "RoHS" at 12634.96,1526.64 h60
  text "OTHER" at 13279.36,1526.64 h60
  text "PER ORDER" at 13676.42,1526.64 h60
  text "ADDITIONAL REQUIREMENTS:" at 11332.46,1385.64 h60
  text "MICROSECTION:" at 11407.23,1270.64 h60
  text "YES" at 12312.96,1270.64 h60
  text "REQUIRED" at 13174.46,1114.49 h60
  text "BARE BOARD ELEC. TEST:" at 11407.23,1111.64 h60
  text "NONE" at 12712.96,1111.64 h60
  text "X" at 13047.46,1111.64 h60
  text "PER ORDER" at 13766.46,1111.64 h60
  text "MANUFACTURER'S UL:" at 11407.23,954.64 h60
  text "RAIL" at 12572.96,950.35 h60
  text "METAL" at 13064.77,950.35 h60
  text "X" at 13440,950 h60
  text "SILK" at 13576.46,950.35 h60
  text ".Layer_Name" at 577,-858.49 h60
M11 Gerber Information:
  lines w10: -292,-930.17 6308,-930.17 ; -292,-726.83 6310,-726.83 ; -292,-523.5 -292,-1133.5 3713,-1133.5 6310,-1133.5 6310,-523.5 -291.5,-523.5 -291.5,-1133.5 1284,-1133.5 ; 2173,-1133.5 2173,-523.5 ; 3440,-726.83 3440,-523.5 ; 4280,-726.83 4280,-523.5 ; 4902,-1140 4902,-937.17
  text "ALL ARTWORK VIEWED FROM TOP SIDE" at -228.5,-655.67 h60
  text "BOARD #:" at 2248,-655.67 h60
  text ".PRJ_Number" at 2793.5,-655.67 h60
  text "REV:" at 3638,-655.67 h60
  text ".PCB_Rev" at 3929.5,-655.67 h60
  text "SVN REV:" at 4476,-655.67 h60
  text ".VersionControl_RevNumber" at 4982,-655.67 h60
  text "LAYER NAME =" at -228.5,-858.49 h60
  text "PLOT NAME =" at -228.5,-1064.34 h60
  text ".plot_File_Name" at 577,-1064.34 h60
  text "GENERATED    :" at 2250,-1064.34 h60
  text ".Print_Date" at 3119.5,-1064.34 h60
  text ".Print_Time" at 3848.5,-1064.34 h60
  text "TEXAS INSTRUMENTS" at 5113,-1064.34 h60
M12 Stackup:
  lines w5: 11355,7737.5 14235,7737.5 ; 11355,7832.7 14235,7832.7 ; 11295,6966 ccw(c11326,6966) 11326,6935 14264,6935 ccw(c14264,6966) 14295,6966 14295,7904 ccw(c14264,7904) 14264,7935 11326,7935 ccw(c11326,7904) 11295,7904 11295,6966
  text "Layer Stack Up Detail for: SAT0084E1-1.PcbDoc" at 11355,7855.15 h39
  text "Layer" at 11355,7797.2 h22
  text "Gerber" at 11968.83,7797.2 h22
  text "Copper" at 12282.82,7797.2 h22
  text "Dielectric" at 12632.74,7797.2 h22
  text "Dielectric" at 12998.05,7797.2 h22
  text "Dielectric" at 13456.93,7797.2 h22
  text "Dielectric" at 13822.24,7797.2 h22
  text "Name" at 11355,7753.2 h22
  text "Document" at 11968.83,7753.2 h22
  text "Thickness" at 12282.82,7753.2 h22
  text "Height" at 12632.74,7753.2 h22
  text "Material" at 12998.05,7753.2 h22
  text "Constant" at 13456.93,7753.2 h22
  text "Type" at 13822.24,7753.2 h22
  text "Top Solder Mask" at 11355,7691.25 h31
  text "(.GTS)" at 11968.83,7691.25 h31
  text "0.4mil" at 12632.74,7691.25 h31
  text "Solder Resist" at 12998.05,7691.25 h31
  text "3.50" at 13456.93,7691.25 h31
  text "Top Layer" at 11355,7603.75 h31
  text "(.GTL)" at 11968.83,7603.75 h31
  text "1.4mil" at 12282.82,7603.75 h31
  text "9.8mil" at 12632.74,7560 h31
  text "FR-4 high TG" at 12998.05,7560 h31
  text "4.20" at 13456.93,7560 h31
  text "Core" at 13822.24,7560 h31
  text "MidLayer1-GND" at 11355,7516.25 h31
  text "(.G1)" at 11968.83,7516.25 h31
  text "1.4mil" at 12282.82,7516.25 h31
  text "9.8mil" at 12632.74,7472.5 h31
  text "FR-4 high TG" at 12998.05,7472.5 h31
  text "4.20" at 13456.93,7472.5 h31
  text "PrePreg" at 13822.24,7472.5 h31
  text "MidLayer2-HiSp" at 11355,7428.75 h31
  text "(.G2)" at 11968.83,7428.75 h31
  text "1.4mil" at 12282.82,7428.75 h31
  text "9.8mil" at 12632.74,7385 h31
  text "FR-4 high TG" at 12998.05,7385 h31
  text "4.20" at 13456.93,7385 h31
  text "Core" at 13822.24,7385 h31
  text "MidLayer3-GND" at 11355,7341.25 h31
  text "(.G3)" at 11968.83,7341.25 h31
  text "1.4mil" at 12282.82,7341.25 h31
  text "9.8mil" at 12632.74,7297.5 h31
  text "FR-4 high TG" at 12998.05,7297.5 h31
  text "4.20" at 13456.93,7297.5 h31
  text "PrePreg" at 13822.24,7297.5 h31
  text "MidLayer4" at 11355,7253.75 h31
  text "(.G4)" at 11968.83,7253.75 h31
  text "1.4mil" at 12282.82,7253.75 h31
  text "9.8mil" at 12632.74,7210 h31
  text "FR-4 high TG" at 12998.05,7210 h31
  text "4.20" at 13456.93,7210 h31
  text "Core" at 13822.24,7210 h31
  text "Bottom Layer" at 11355,7166.25 h31
  text "(.GBL)" at 11968.83,7166.25 h31
  text "1.4mil" at 12282.82,7166.25 h31
  text "Bottom Solder Mask" at 11355,7078.75 h31
  text "(.GBS)" at 11968.83,7078.75 h31
  text "0.4mil" at 12632.74,7078.75 h31
  text "Solder Resist" at 12998.05,7078.75 h31
  text "3.50" at 13456.93,7078.75 h31
  text ".Layer_Name" at 577,-858.49 h60
M13 Component Bodies Top:
  text ".Layer_Name" at 577,-858.49 h60
M14 Component Bodies Bottom:
  text ".Layer_Name" at 577,-858.49 h60
M15 Courtyards Top:
  text ".Layer_Name" at 577,-858.49 h60
M16 Courtyards Bottom:
  text ".Layer_Name" at 577,-858.49 h60
Drill Drawing:
  text ".legend" at 7332.5,215.5 h60
  text "Drill Table" at 7357.5,30.5 h60
  text ".Layer_Name" at 577,-858.49 h60

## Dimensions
0,0 to 7055,0 on M2 Board Dimensions
0,0 to 0,5555 on M2 Board Dimensions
